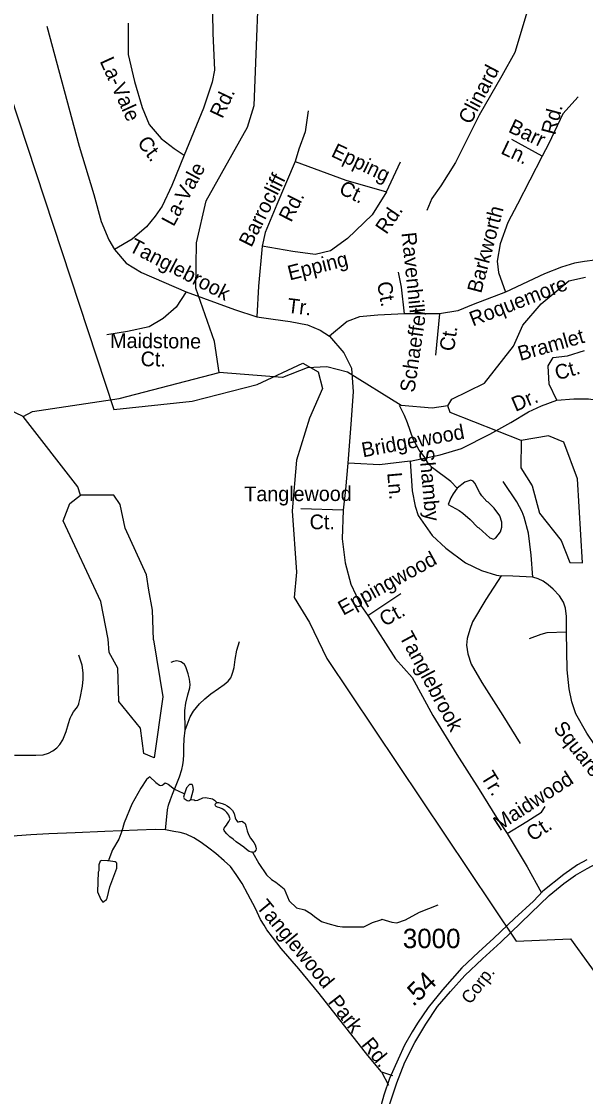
# Model space of a CAD drawing. Extents: x 1547597 to 1699558, y 810033 to 920809.
# Drawn here: x 1584631 to 1588265, y 818935 to 825864 of the extents above; entities that cross this region are included whole.
import ezdxf

# ---------------------------------------------------------------- set-up
doc = ezdxf.new("R2010")
doc.units = 0
for name, color, linetype in [('Exist Boundary Political City Limit New', 7, 'Continuous'), ('Exist Hydrographic Creek Single Shore', 7, 'Continuous'), ('Exist Hydrographic Misc Water Feature', 7, 'Continuous'), ('Exist Hydrographic Pond Under 1500 Sq Ft', 7, 'Continuous'), ('Exist Railroad Mainline', 7, 'Continuous'), ('Exist Railroad Mainline Label', 7, 'Continuous'), ('Exist Road Non-System Type 51', 7, 'Continuous'), ('Exist Road Non-System Type 51 Label', 7, 'Continuous'), ('Exist Road Secondary Mileage Hundredths English Label', 7, 'Continuous'), ('Exist Road Secondary Type 51 Attributed', 7, 'Continuous'), ('Exist Road Secondary Type 51 Number Label', 7, 'Continuous'), ('Map Preparation Boundary City Limit Buffer Line', 7, 'Continuous')]:
    doc.layers.add(name, color=color, linetype=linetype)

msp = doc.modelspace()

# ---------------------------------------------------------------- linework, layer by layer
at = {"layer": 'Exist Boundary Political City Limit New'}
msp.add_lwpolyline([(1584385.4, 825907.6), (1585225.9, 823361.7), (1585730.1, 823416.1), (1586150.3, 823524.8), (1586444.5, 823660.7), (1586542.6, 823606.3), (1586570.6, 823497.6), (1586486.5, 823307.3), (1586402.5, 823035.5), (1586374.5, 822709.3), (1586402.5, 822315.1), (1586388.5, 822152), (1586486.5, 821988.9), (1586598.6, 821757.8), (1587817.2, 819936.5), (1588167.4, 819950.1), (1588405.5, 819623.9), (1588783.7, 819596.7), (1588979.8, 819542.3), (1589183, 819449.9), (1589351.1, 819341.1), (1589505.1, 819137.2), (1589907.2, 818618.7)], dxfattribs=at)
at = {"layer": 'Exist Hydrographic Creek Single Shore'}
for points in [[(1585905.5, 823600.3), (1585874.6, 823801.2), (1585754.6, 824145), (1585759.5, 824437.1), (1585821.5, 824708.3), (1586086.6, 825182.1), (1586130.6, 825322.4), (1586170.5, 826372), (1586175.6, 826723.2), (1586090.6, 827158.2), (1586084.5, 827338.9), (1585741.6, 827838.2), (1585743.5, 827962.9), (1585913.5, 828169.6), (1585956.6, 828283.6), (1586101.5, 828490.7)], [(1587377.6, 823386.6), (1587403.5, 823428.8), (1587613.6, 823532.8), (1587800.6, 823772), (1587860.6, 823905.4), (1587979.6, 824044.1), (1588156.6, 824191.5), (1588265.6, 824215.6)], [(1584642.6, 823317.3), (1584352.6, 823454.5), (1584245.5, 823564.9), (1584156.5, 823707.9), (1584040.6, 823818.6), (1583932.5, 823820.8), (1583806.5, 823780.6), (1583680.5, 823665), (1583505.6, 823668.6), (1583297.6, 823712.2), (1583039.5, 823724), (1582948.6, 823775.1), (1582790.6, 823804.5), (1582498.6, 823790.7), (1582175.5, 823945), (1581965.5, 823873.7)], [(1587377.6, 823386.6), (1587277.5, 823372.2), (1587077.6, 823389.4), (1586730.5, 823603.2), (1586597.6, 823638.8), (1586472.6, 823631.5), (1586313.6, 823569), (1585905.5, 823600.3)], [(1584642.6, 823317.3), (1584701.6, 823348.9), (1585260.5, 823432.8), (1585905.5, 823600.3)]]:
    msp.add_lwpolyline(points, dxfattribs=at)
at = {"layer": 'Exist Hydrographic Misc Water Feature'}
for points in [[(1587438.1, 822856.2), (1587396.5, 822899.2), (1587279.5, 822986.6), (1587249.9, 823018.9), (1587224.4, 823059.2), (1587192.8, 823099.6), (1587153.8, 823172.1), (1587117, 823276.5), (1587097.6, 823324.7), (1587066.5, 823388.7)], [(1587849.6, 823163.6), (1587393.6, 823343.6), (1587377.6, 823386.6)], [(1585010.6, 822810.9), (1584994.6, 822863.7), (1584642.6, 823317.3)], [(1587438.1, 822856.2), (1587411.5, 822819), (1587397.2, 822793.2), (1587380.6, 822749.6), (1587450.2, 822712.6), (1587474, 822694.3), (1587521.5, 822653.7), (1587568.9, 822605.1), (1587576.9, 822601), (1587648.1, 822536.2), (1587671.9, 822527.9), (1587688, 822535.7), (1587716.5, 822573.3), (1587724.8, 822605.2), (1587725.3, 822637.1), (1587713.8, 822677.3), (1587676.3, 822727.7), (1587636.8, 822766.2), (1587628.9, 822770.3), (1587597.3, 822806.7), (1587583.6, 822824.8), (1587552.3, 822887.2), (1587540.4, 822901.3), (1587526.6, 822907.5), (1587488.3, 822894), (1587438.1, 822856.2)], [(1585457.3, 820994.7), (1585437, 820977.1), (1585400.2, 820921.2), (1585342.7, 820818.1), (1585292.9, 820698.5), (1585278.3, 820644.6), (1585257.6, 820593.3), (1585216.5, 820523.6), (1585193.5, 820462.5), (1585191.3, 820454.3)], [(1585457.3, 820994.7), (1585496.7, 820957.8), (1585520.6, 820941.7), (1585528.5, 820939.9), (1585536.6, 820941.4), (1585544.7, 820945.3), (1585556.8, 820957.4)], [(1585556.8, 820957.4), (1585576.7, 820947.1), (1585616.3, 820916), (1585672, 820889.4), (1585681.9, 820885.1)], [(1585721.5, 820849), (1585738.4, 820914.3), (1585734.7, 820938.2), (1585730.8, 820944.8), (1585712.8, 820946.8), (1585694.4, 820925), (1585686.1, 820898.9), (1585681.9, 820885.1)], [(1585681.9, 820885.1), (1585679.8, 820879.4), (1585675.6, 820863.1), (1585679.6, 820855.6), (1585697.3, 820842.9), (1585709.2, 820841.1), (1585721.5, 820849)], [(1585721.5, 820849), (1585743.3, 820846.1), (1585749.2, 820841.9), (1585767.3, 820845.6), (1585799.6, 820859.7), (1585815.6, 820861.1), (1585861.4, 820854.4), (1585875.4, 820844.3), (1585889.1, 820830.1)], [(1586118.5, 820508.6), (1586112.5, 820508.7), (1586098.7, 820514.7), (1586080.9, 820527.4), (1586063, 820541.7), (1586041.4, 820557.8), (1586013.6, 820576.4), (1585993.8, 820592.4), (1585974, 820609.2), (1585954.3, 820626.8), (1585940.5, 820643.5), (1585936.5, 820649.3), (1585934.5, 820655.1), (1585936.8, 820663.3), (1585942.9, 820673), (1585951.1, 820683.5), (1585959.1, 820694.8), (1585967.4, 820707), (1585971.5, 820716.8), (1585975.5, 820724.9), (1585971.9, 820734.8), (1585966, 820747.2), (1585954.2, 820765.5), (1585940.4, 820777.3), (1585924.6, 820789.9), (1585908.7, 820796), (1585892.8, 820800.4), (1585884.9, 820804.7), (1585880.8, 820808.1), (1585879, 820816.3), (1585883.1, 820826.1), (1585889.1, 820830.1)], [(1585889.1, 820830.1), (1585901.2, 820829.8), (1585923.1, 820823.6), (1585940.9, 820815.9), (1585957, 820807.3), (1585970.7, 820797.2), (1585980.6, 820788.8), (1585990.4, 820778.7), (1586000.3, 820758.8), (1586007.7, 820730.8), (1586011.6, 820720), (1586017.6, 820712.6), (1586023.4, 820705.8), (1586029.4, 820704.1), (1586035.5, 820708), (1586041.5, 820707.9), (1586051.4, 820710.2), (1586061.4, 820703.4), (1586071.2, 820693.4), (1586079, 820673.5), (1586084.6, 820647.1), (1586094.2, 820623.2), (1586106.1, 820600.8), (1586121.6, 820580.8), (1586127.6, 820572.5), (1586137.3, 820556.7), (1586141.1, 820542.6), (1586143, 820530.3), (1586140.7, 820522.1), (1586132.7, 820512.4), (1586124.6, 820508.5), (1586118.5, 820508.6)], [(1586118.5, 820508.6), (1586159.5, 820436.4), (1586210.5, 820363.1), (1586242.1, 820333), (1586269.9, 820316.8), (1586323.2, 820273.8), (1586356.1, 820195.2), (1586403.6, 820150.8), (1586455.5, 820137.4), (1586495, 820115.3), (1586518.8, 820095.1), (1586564.4, 820063.8), (1586604, 820049.9), (1586667.9, 820033), (1586699.8, 820028.2), (1586835.8, 820027.9), (1586892.4, 820055.5), (1586946.8, 820072.5), (1586952.8, 820078.1), (1587016.4, 820057.9), (1587048.4, 820054.9), (1587104.8, 820074.2), (1587195.4, 820123.2), (1587316.2, 820170.9)], [(1585191.3, 820454.3), (1585185.4, 820454.4), (1585145.4, 820456.9), (1585137.3, 820451.3), (1585129, 820426.9), (1585128.5, 820389.1), (1585124.4, 820381), (1585120.4, 820253.1), (1585141.7, 820205.1), (1585155.5, 820186.7), (1585179.6, 820204.3), (1585183.9, 820214), (1585201.1, 820285.9), (1585244.7, 820405.7), (1585245.1, 820437.7), (1585241.4, 820443.5), (1585233.5, 820447.7), (1585205.4, 820451.6), (1585191.3, 820454.3)]]:
    msp.add_lwpolyline(points, dxfattribs=at)
at = {"layer": 'Exist Hydrographic Pond Under 1500 Sq Ft'}
for points in [[(1587849.6, 823163.6), (1587847.6, 822986.5), (1587920.6, 822870.1), (1587967.5, 822695.2), (1588107.6, 822518.3), (1588163.6, 822376), (1588246.6, 822374.4), (1588212.6, 822916.7), (1588124.6, 823151.5), (1588025.6, 823193), (1587849.6, 823163.6)], [(1585188.6, 821882.2), (1585141.6, 822125.4), (1584899.5, 822645.7), (1584942.6, 822756.4), (1585010.6, 822810.9)], [(1585480.5, 821877.9), (1585475.8, 822068.4), (1585451.5, 822197.9), (1585436.6, 822296.7), (1585298.6, 822598.2), (1585267.6, 822749.9), (1585226.6, 822809.7), (1585010.6, 822810.9)], [(1585480.5, 821877.9), (1585541.6, 821510), (1585486.6, 821117.2), (1585419.5, 821144.8), (1585397.6, 821309.4), (1585257.6, 821479.7), (1585252.5, 821696.4), (1585195.5, 821796), (1585188.6, 821882.2)]]:
    msp.add_lwpolyline(points, dxfattribs=at)
at = {"layer": 'Exist Railroad Mainline'}
msp.add_lwpolyline([(1586998.8, 818868), (1587049.1, 819023.8), (1587101.4, 819156.6), (1587165.8, 819283.3), (1587235.7, 819400.5), (1587311.1, 819514.1), (1587394.5, 819610.7), (1587486.6, 819713.7), (1587600.2, 819821.3), (1587719.9, 819930), (1587913, 820116), (1588030.6, 820229.7), (1588126.2, 820307.1), (1588200.1, 820360.9), (1588275.5, 820405.1), (1588363, 820452.4), (1588437.4, 820490.6), (1588515.9, 820518.8), (1588604.4, 820549), (1588698.9, 820571.1), (1588789.4, 820587.2), (1588947.3, 820610.3), (1589126.3, 820634.4), (1589252.5, 820657.1)], dxfattribs=at)
at = {"layer": 'Exist Road Non-System Type 51'}
for q in [(1586996.4, 819007.4), (1587021.3, 819070.9)]:
    msp.add_line((1586949.5, 819094), q, dxfattribs=at)
for points in [[(1585860.3, 826042.3), (1585864.1, 825788), (1585875.5, 825548.9), (1585860.3, 825472.9), (1585803.4, 825305.9), (1585678.3, 825002.3)], [(1587907.8, 825992.1), (1587808.8, 825664.2), (1587726.3, 825513.2), (1587580.1, 825260.7), (1587427.5, 824955.5), (1587333.2, 824804.5), (1587274.3, 824721.9), (1587243.6, 824646.4)], [(1585318, 825852.5), (1585318, 825651.3), (1585359.7, 825476.7), (1585409, 825309.7), (1585454.5, 825199.7), (1585530.4, 825108.6), (1585613.8, 825044), (1585678.3, 825002.3)], [(1584794.6, 825833.5), (1585003.2, 825059.2), (1585098, 824748), (1585143.5, 824573.4), (1585192.8, 824455.7), (1585230.8, 824395)], [(1588217.2, 825377.2), (1588118.2, 825268.6), (1588028.6, 825077.5), (1587986.1, 824995)], [(1586477.4, 825288.4), (1586458.5, 825151.8), (1586416.8, 825041.7), (1586394, 824962)], [(1587986.1, 824995), (1587790.5, 825103.5)], [(1585678.3, 825002.3), (1585598.7, 824805.9), (1585538.1, 824673.1), (1585492.5, 824608.6), (1585435.7, 824540.2), (1585344.6, 824460.5), (1585230.8, 824395)], [(1586394, 824962), (1586276.4, 824684.9), (1586200.6, 824502.7), (1586181.6, 824415.4)], [(1586394, 824962), (1586720.2, 824840.5), (1586981.9, 824764.6)], [(1586981.9, 824764.6), (1587072.9, 824958.2)], [(1587986.1, 824995), (1587825.9, 824687), (1587764.6, 824569), (1587715.1, 824429.8), (1587696.3, 824318.9), (1587704.4, 824245.1), (1587749.9, 824119.8)], [(1586981.9, 824764.6), (1586890.8, 824616.6), (1586731.5, 824464.8), (1586621.6, 824385), (1586523, 824362.3), (1586378.8, 824381.2), (1586181.6, 824415.4)], [(1585230.8, 824395), (1585305.6, 824306.1), (1585404.2, 824245.4), (1585692.4, 824120.1)], [(1586181.6, 824415.4), (1586158.9, 824157.3), (1586147.6, 823960.7)], [(1588591.9, 824359), (1588258.1, 824317.2), (1588193.6, 824305.8), (1588110.2, 824279.3), (1588000.2, 824237.5), (1587749.9, 824119.8)], [(1587097.6, 823979.4), (1587078.6, 824150.2), (1587059.6, 824248.9)], [(1585692.4, 824120.1), (1585628, 824021.4), (1585544.5, 823949.3), (1585453.5, 823896.2), (1585313.2, 823865.8), (1585180.4, 823843)], [(1585692.4, 824120.1), (1586003.4, 824006.2), (1586147.6, 823960.7)], [(1587749.9, 824119.8), (1587541.3, 824040.1), (1587442.7, 823998.4), (1587325.1, 823979.4)], [(1587097.6, 823979.4), (1586926.9, 823971.8), (1586809.3, 823960.4), (1586729.7, 823930.1), (1586615.9, 823835.2)], [(1587325.1, 823979.4), (1587097.6, 823979.4)], [(1587325.1, 823979.4), (1587298.6, 823713.7)], [(1586147.6, 823960.7), (1586252.7, 823945.8), (1586362.7, 823930.6), (1586472.7, 823907.9), (1586556.1, 823873.7), (1586615.9, 823835.2)], [(1586615.9, 823835.2), (1586707.8, 823727.3), (1586757.1, 823628.6), (1586768.5, 823476.8), (1586753.4, 823268), (1586734.4, 823017.5)], [(1588080.2, 823423.6), (1588030.9, 823526.1), (1588023.3, 823643.8), (1588057.4, 823696.9), (1588148.4, 823708.3), (1588258.4, 823742.4)], [(1587135.8, 823028.9), (1587329.2, 823070.6), (1587465.8, 823112.4), (1587647.8, 823203.5), (1587784.3, 823279.4), (1587898.1, 823347.7), (1587981.6, 823385.7), (1588080.2, 823423.6)], [(1588080.2, 823423.6), (1588188.9, 823432.1), (1588283.7, 823432.1), (1588443, 823409.4), (1588541.6, 823371.4), (1588628.9, 823322.1), (1588655.4, 823303.1)], [(1586734.4, 823017.5), (1586719.2, 822846.7), (1586704.1, 822713.9)], [(1587135.8, 823028.9), (1586938.6, 823006.1), (1586775.5, 823013.7), (1586734.4, 823017.5)], [(1587135.8, 823028.9), (1587147.2, 822839.1), (1587167.8, 822739.7), (1587187.5, 822678.6), (1587276.1, 822550.6), (1587365.5, 822468.2), (1587491.4, 822374.7), (1587593.9, 822324.3), (1587691, 822295.6), (1587720.7, 822290.2)], [(1587924.7, 822281.2), (1587914, 822423.2), (1587896.9, 822565.3), (1587869.9, 822669.6), (1587857.3, 822703.7), (1587823.2, 822766.7), (1587734.2, 822899.7)], [(1586704.1, 822713.9), (1586431, 822722.9)], [(1586704.1, 822713.9), (1586696.5, 822529.3), (1586715.5, 822373.7), (1586753.4, 822237), (1586817.9, 822100.4), (1586863.4, 822035.9)], [(1587720.7, 822290.2), (1587621.8, 822139.1), (1587537.3, 821993.5), (1587520.2, 821945), (1587502.2, 821887.4), (1587498.6, 821844.3), (1587507.6, 821788.5), (1587529.2, 821722), (1587596.6, 821603.3), (1587733.3, 821391.1), (1587843.8, 821209.5)], [(1587924.7, 822281.2), (1587797.1, 822288.4), (1587720.7, 822290.2)], [(1588142.3, 821927), (1588142.3, 822027.7), (1588135.1, 822081.6), (1588122.5, 822121.2), (1588097.4, 822160.7), (1588056, 822205.7), (1588023.6, 822232.6), (1587993.1, 822256), (1587958.9, 822270.4), (1587924.7, 822281.2)], [(1586863.4, 822035.9), (1587075.8, 822176.3)], [(1586863.4, 822035.9), (1587041.6, 821755), (1587149, 821635.6), (1587281, 821390.7), (1587436.8, 821140.1), (1587579.3, 820914), (1587690.5, 820732.2), (1587760.6, 820629)], [(1588142.3, 821927), (1588014.7, 821923.4), (1587976.9, 821912.6), (1587901.4, 821885.6)], [(1588403.9, 821104.5), (1588375, 821125.7), (1588349.4, 821157.4), (1588322.1, 821203.9), (1588272.7, 821276.1), (1588202.5, 821401.9), (1588177.4, 821479.3), (1588159.4, 821562), (1588145.9, 821684.2), (1588142.3, 821927)], [(1585685.4, 821295), (1585718.7, 821382.3), (1585740.1, 821418), (1585778.1, 821465.5), (1585812.6, 821498.9), (1585851, 821530), (1585899.6, 821563.5), (1585936.3, 821591), (1585962.3, 821612.4), (1585978.8, 821634.1), (1585987, 821650), (1585993.3, 821669.9), (1586001.8, 821699.6), (1586006.8, 821751.7), (1586017.5, 821811.6), (1586034.7, 821866.7)], [(1584584.8, 821134.8), (1584644.5, 821133.9), (1584722.6, 821134.6), (1584770.6, 821137.6), (1584805, 821147.4), (1584833.2, 821162.6), (1584859.5, 821182.4), (1584877.7, 821204.1), (1584896.3, 821233.5), (1584918.4, 821287.9), (1584932.9, 821339.5), (1584944.4, 821373.1), (1584952.7, 821391), (1584966.9, 821414.6), (1584991.9, 821446.3), (1584999.8, 821466.2), (1584999.9, 821468.1), (1585008.8, 821502.1), (1585023.8, 821579.6), (1585028.7, 821625.4), (1585029.1, 821665.5), (1585022, 821715.8), (1585001.3, 821779.9)], [(1585685.4, 821295), (1585682.7, 821422.5), (1585689.3, 821470.2), (1585702.5, 821524.1), (1585715.6, 821569.8), (1585717.9, 821589.8), (1585713.7, 821624.7), (1585704.9, 821660), (1585690.1, 821704.6), (1585680.9, 821719.9), (1585668.6, 821730.6), (1585656.6, 821736.8), (1585630.8, 821743.6), (1585610.6, 821737.7), (1585592.5, 821732.5)], [(1585558.8, 820652.9), (1585568.4, 820736.7), (1585570.9, 820782.6), (1585577.5, 820812.7), (1585590, 820848.6), (1585604.8, 820884), (1585627.3, 820941.7), (1585648.5, 820995.4), (1585663.2, 821043.4), (1585669.7, 821073.1), (1585674.3, 821102.9), (1585676.6, 821139), (1585676.9, 821186.5), (1585678.4, 821241), (1585685.4, 821295)], [(1587760.6, 820629), (1587887.9, 820706.8), (1587981, 820767.3), (1588005.4, 820804.9)], [(1585558.8, 820652.9), (1585492.9, 820656.2), (1585378.9, 820651.9), (1585168.6, 820643.4), (1584976.4, 820634.5), (1584806.6, 820627.1), (1584690.2, 820621.2), (1584602.1, 820614.5), (1584546.2, 820607.4), (1584510, 820606.2)], [(1586949.5, 819094), (1586863.4, 819199.5), (1586729.9, 819369.6), (1586547.8, 819598.8), (1586418.4, 819756.7), (1586304.5, 819888.7), (1586247.9, 819961.7), (1586212.4, 820008.1), (1586195, 820038.6), (1586171.8, 820074.9), (1586138.7, 820145.5), (1586090, 820238), (1586053.4, 820307.1), (1586014.2, 820365.6), (1585977.1, 820416.3), (1585937.5, 820454.8), (1585882.3, 820501.6), (1585838.7, 820535.9), (1585787.6, 820571.1), (1585740.9, 820602.9), (1585692.5, 820624.9), (1585652.7, 820635.6), (1585612.7, 820642), (1585558.8, 820652.9)], [(1587760.6, 820629), (1587889.2, 820415), (1587980.4, 820246.7)]]:
    msp.add_lwpolyline(points, dxfattribs=at)
at = {"layer": 'Exist Road Secondary Type 51 Attributed'}
msp.add_lwpolyline([(1588274.5, 820460.5), (1588213.2, 820427.3), (1588125.7, 820365.9), (1587990.4, 820257.8), (1587930.6, 820192.9), (1587806.9, 820082.3), (1587674.1, 819955.6), (1587575.1, 819865.6), (1587467.5, 819764), (1587343.8, 819622.2), (1587250.7, 819508.1), (1587183.4, 819408.5), (1587148.7, 819350.7), (1587099.4, 819265.2), (1587057.1, 819175.7), (1587001.8, 819051), (1586965.1, 818943.9), (1586931.9, 818819.2)], dxfattribs=at)
at = {"layer": 'Map Preparation Boundary City Limit Buffer Line'}
msp.add_lwpolyline([(1584385.4, 825907.6), (1585225.9, 823361.7), (1585730.1, 823416.1), (1586150.3, 823524.8), (1586444.5, 823660.7), (1586542.6, 823606.3), (1586570.6, 823497.6), (1586486.5, 823307.3), (1586402.5, 823035.5), (1586374.5, 822709.3), (1586402.5, 822315.1), (1586388.5, 822152), (1586486.5, 821988.9), (1586598.6, 821757.8), (1587817.2, 819936.5), (1588167.4, 819950.1), (1588405.5, 819623.9), (1588783.7, 819596.7), (1588979.8, 819542.3), (1589183, 819449.9), (1589351.1, 819341.1), (1589505.1, 819137.2), (1589907.2, 818618.7)], dxfattribs=at)

# ---------------------------------------------------------------- texts
at = {"layer": 'Exist Railroad Mainline Label'}
msp.add_text('Corp.', height=82.02, rotation=52.34662, dxfattribs=at).set_placement((1587522.2, 819524.1))
at = {"layer": 'Exist Road Non-System Type 51 Label'}
for s, rotation, p in [('La-Vale', 294.54088, (1585133, 825608.1)), ('Clinard', 62.26236, (1587524.3, 825194.8)), ('Rd.', 64.64705, (1585925.1, 825232.8)), ('Rd.', 75.21352, (1588069.1, 825127.6)), ('Barr', 334.63821, (1587761.4, 825153.7)), ('Ct.', 306.64495, (1585372.5, 825081.6)), ('Epping', 334.15893, (1586620.1, 824997)), ('Ln.', 334.63821, (1587713.3, 825015)), ('La-Vale', 61.64959, (1585611.1, 824536.8)), ('Barrocliff', 63.43495, (1586111.2, 824403.5)), ('Ct.', 334.15893, (1586669.5, 824758.1)), ('Rd.', 63.36152, (1586368.2, 824565)), ('Rd.', 55.7506, (1586982.3, 824486.2)), ('Barkworth', 75.21352, (1587592.5, 824107.4)), ('Tanglebrook', 332.64715, (1585316.4, 824386.2)), ('Ravenhill', 275.92227, (1587079, 824500.8)), ('Epping', 14.16725, (1586359.2, 824194.3)), ('Ct.', 280.47419, (1586920.9, 824179)), ('Roquemore', 21.21851, (1587539.1, 823897.2)), ('Tr.', 353.01326, (1586339.6, 823987.2)), ('Schaeffer', 81.64204, (1587162.3, 823468.9)), ('Maidstone', 359.54997, (1585201.7, 823759.8)), ('Ct.', 81.64204, (1587417, 823734.2)), ('Bramlet', 15.90877, (1587844.3, 823675.1)), ('Ct.', 359.29364, (1585398.2, 823641.7)), ('Ct.', 15.90877, (1588082.5, 823550.2)), ('Dr.', 23.24006, (1587813.8, 823346.9)), ('Bridgewood', 10.42703, (1586831.2, 823054.1)), ('Shamby', 275.10554, (1587192.1, 823105)), ('Ln.', 275.10554, (1586987.2, 822953.8)), ('Tanglewood', 0.17709, (1586066.5, 822771.2)), ('Ct.', 0.17709, (1586487.6, 822590.6)), ('Eppingwood', 28.84849, (1586703.6, 822033)), ('Ct.', 28.84849, (1586969.7, 821961.2)), ('Tanglebrook', 298.33613, (1587062.5, 821899.7)), ('Squarewood', 308.2027, (1588053.6, 821307.7)), ('Tr.', 301.45219, (1587586.9, 820995.8)), ('Maidwood', 32.99946, (1587710.3, 820642.8)), ('Ct.', 32.99946, (1587922.4, 820575.9)), ('Tanglewood', 309.58384, (1586139.7, 820156.1)), ('Park', 307.78364, (1586601.8, 819543.1)), ('Rd.', 309.34001, (1586816.1, 819266.9))]:
    msp.add_text(s, height=95, rotation=rotation, dxfattribs=at).set_placement(p)
at = {"layer": 'Exist Road Secondary Mileage Hundredths English Label'}
msp.add_text('.54', height=120, rotation=44.05724, dxfattribs=at).set_placement((1587155, 819509.6))
at = {"layer": 'Exist Road Secondary Type 51 Number Label'}
msp.add_text('3000', height=125, dxfattribs=at).set_placement((1587087.9, 819891.1))

doc.saveas('drawing.dxf')
